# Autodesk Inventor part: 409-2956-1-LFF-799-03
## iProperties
Created: 2010-11
Part Number: 409-2956-1-LFF-799-03
Material: 3/4" OD TUBE - SS
Document SubType Name: Modeling
Designer: S. Boerckel
Engineer: Steve Boerckel
Mass: 309.983 g
Surface Area: 466.545 cm^2
Volume: 38.3643 cm^3
Density: 8.08 g/cm^3
Description: DRAIN TUBING
Length: 10.043 in
Author: S. Boerckel
Revision Number: 0
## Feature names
1. Sweep1
